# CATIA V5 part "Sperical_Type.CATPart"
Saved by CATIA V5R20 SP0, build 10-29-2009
Part number: Sperical_Type
Bounding box of the stored display mesh (mm): x -2.5 to 37.5, y -19.994 to 19.994, z -21.762 to 31.311
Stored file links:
  G:\Khaled_CFAO_2011\SIL\SIL_GR1\gperrin\Khaled\CAD_CATIA\Khaled\Sperical_Type.CATPart
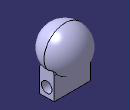
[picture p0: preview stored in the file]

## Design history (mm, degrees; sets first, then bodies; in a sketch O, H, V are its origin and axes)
AxisSystem1: origin (0, 0, 0), X (1, 0, 0), Y (0, 1, 0), Z (0, 0, 1)
Body1 (main body)
  Sketch1 on YZ plane of AxisSystem1, origin (0, 0, 0), H (0, 1, 0), V (0, 0, 1)
    point P1 (-7, -21.7619)
    line L1 (-7, -21.7619) -> (-7, 0)
    point P2 (-7, 0)
    arc A1 centre (-3.5, 0) radius 3.5 from (-7, 0) to (-4.8284, 3.2381) cw
    point P4 (-4.8284, 3.2381)
    line L2 (-4.8284, 3.2381) -> (-5, 3.2381)
    point P5 (-5, 3.2381)
    line L3 (-5, 3.2381) -> (-5, 11.3114)
    point P6 (-5, 11.3114)
    line L4 (-5, 11.3114) -> (0, 11.3114)
    point P7 (0, 11.3114)
    line L5 (-7, -21.7619) -> (0, -21.7619)
    point P8 (0, -21.7619)
    reference intersected line E1 through (0, 0) direction (0, 1) from ZX plane of AxisSystem1
    point P11 (7, -21.7619)
    point P12 (7, 0)
    point P14 (4.8284, 3.2381)
    point P15 (5, 3.2381)
    point P16 (5, 11.3114)
    point P17 (0, 11.3114)
    point P18 (0, -21.7619)
    line L6 (7, -21.7619) -> (7, 0)
    arc A2 centre (3.5, 0) radius 3.5 from (7, 0) to (4.8284, 3.2381) ccw
    line L7 (4.8284, 3.2381) -> (5, 3.2381)
    line L8 (5, 3.2381) -> (5, 11.3114)
    line L9 (5, 11.3114) -> (0, 11.3114)
    line L10 (7, -21.7619) -> (0, -21.7619)
    length L10 = 7
    distance P14 L10 = 25
    length L9 = 5
    coincidence: P2 H, A1 O, P7 V, P8 V, P7 P17, P8 P18
    vertical: L1 V, L3 V
    tangency: A1 L1
    horizontal: L2 H, L4 H, L5 H
    symmetry: P1 P11 E1, P2 P12 E1, P4 P14 E1, P5 P15 E1, P6 P16 E1, P7 P17 E1, P8 P18 E1, L1 L6 E1, A1 A2 E1, L2 L7 E1, L3 L8 E1, L4 L9 E1, L5 L10 E1
  Pad1: profile Sketch1, direction (1, 0, 0), length 35
  Sketch2 on end face of Pad1, origin (35, 0, 0), H (0, 1, 0), V (0, 0, 1)
    circle A1 centre (0, -13) radius 5
    point P1 (0, -13)
    point P2 (0, 0)
    radius A1 = 5
    distance P1 H = 13
    coincidence: P1 V
  Point1: type Center, Curve Sketch2
  Sketch3 on end face of Pad1, origin (35, 0, -5), H (0, 1, 0), V (0, 0, 1)
    point P1 (0, -8)
    reference projected point E1 (0, -8) from Point1
    coincidence: E1 P1
  Hole1: placed by Sketch3, at (35, 0, -13) direction (-1, 0, 0), diameter 10, through (limit type 3)
  Point2: type OnCurve, Support edge [face of Pad1 from Sketch1.L4 | face of Pad1 from Sketch1.L9], Ratio 0.5
  Sphere1: Center Point2, Axis AxisSystem1, Radius 20, Angle1 -45, Angle3 0, Angle4 180
  CloseSurface1: CloseElement Sphere1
